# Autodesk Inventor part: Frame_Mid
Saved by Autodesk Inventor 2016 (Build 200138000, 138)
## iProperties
Created: 2016-03
Part Number: Frame_Mid
Material: Generic
Document SubType Name: Modeling
Designer: bongo_000
Density: 1 g/cm^3
Appearance: Default
Author: bongo_000
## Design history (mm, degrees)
feature "SOLID1"
body "Solid1"
